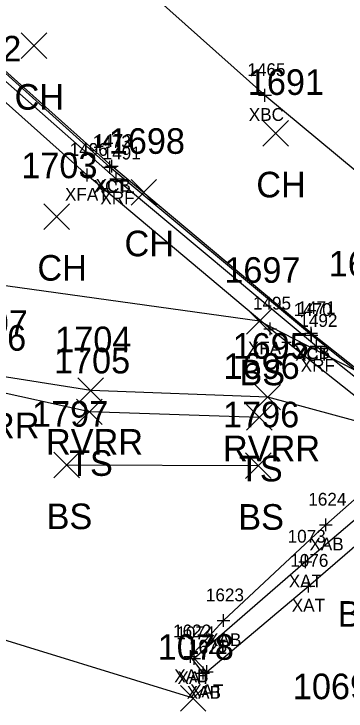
# Model space of a CAD drawing. Extents: x 1616726 to 1619875, y 273782 to 276557.
# Drawn here: x 1616995.8 to 1617021.7, y 276211.5 to 276265.9 of the extents above; entities that cross this region are included whole.
import ezdxf

# ---------------------------------------------------------------- set-up
doc = ezdxf.new("R2010")
doc.units = 0
for name, color, linetype in [('B_A', 7, 'Continuous'), ('B_I', 7, 'Continuous'), ('B_TIC', 7, 'Continuous'), ('BDC', 7, 'Continuous'), ('BELB', 7, 'Continuous'), ('BF', 7, 'Continuous'), ('BR', 7, 'Continuous'), ('BSUBM', 7, 'Continuous'), ('L_A', 7, 'Continuous'), ('L_I', 7, 'Continuous'), ('L_TIC', 7, 'Continuous'), ('LAWE', 7, 'Continuous'), ('LELB', 7, 'Continuous'), ('S_C', 7, 'Continuous')]:
    doc.layers.add(name, color=color, linetype=linetype)

msp = doc.modelspace()

# ---------------------------------------------------------------- linework, layer by layer
at = {"layer": 'B_TIC'}
for p, q in [((1617015.413, 276259.543), (1617015.488, 276259.543)), ((1617003.313, 276253.921), (1617003.388, 276253.921)), ((1617003.452, 276254.007), (1617003.528, 276254.007)), ((1617001.54, 276253.314), (1617001.616, 276253.314)), ((1617003.801, 276253.031), (1617003.877, 276253.031)), ((1617015.82, 276241.312), (1617015.895, 276241.312)), ((1617019.015, 276240.957), (1617019.09, 276240.957)), ((1617019.043, 276240.812), (1617019.119, 276240.812)), ((1617019.442, 276239.958), (1617019.518, 276239.958)), ((1617020.165, 276225.998), (1617020.241, 276225.998)), ((1617018.568, 276223.108), (1617018.643, 276223.108)), ((1617018.802, 276221.224), (1617018.878, 276221.224)), ((1617012.168, 276218.528), (1617012.244, 276218.528)), ((1617009.608, 276215.712), (1617009.683, 276215.712)), ((1617009.878, 276215.569), (1617009.953, 276215.569)), ((1617010.87, 276214.533), (1617010.945, 276214.533)), ((1617010.581, 276214.426), (1617010.656, 276214.426))]:
    msp.add_line(p, q, dxfattribs=at)
for points in [[(1617015.409, 276259.043), (1617015.409, 276260.044)], [(1617014.909, 276259.543), (1617015.909, 276259.543)], [(1617003.309, 276253.421), (1617003.309, 276254.421)], [(1617003.449, 276253.507), (1617003.449, 276254.507)], [(1617001.537, 276252.814), (1617001.537, 276253.814)], [(1617002.809, 276253.921), (1617003.809, 276253.921)], [(1617002.949, 276254.007), (1617003.949, 276254.007)], [(1617001.037, 276253.314), (1617002.037, 276253.314)], [(1617003.798, 276252.531), (1617003.798, 276253.531)], [(1617003.298, 276253.031), (1617004.298, 276253.031)], [(1617015.816, 276240.812), (1617015.816, 276241.812)], [(1617015.316, 276241.312), (1617016.316, 276241.312)], [(1617019.011, 276240.457), (1617019.011, 276241.457)], [(1617019.04, 276240.312), (1617019.04, 276241.312)], [(1617018.511, 276240.957), (1617019.511, 276240.957)], [(1617018.54, 276240.812), (1617019.54, 276240.812)], [(1617019.439, 276239.458), (1617019.439, 276240.458)], [(1617018.939, 276239.958), (1617019.939, 276239.958)], [(1617020.162, 276225.498), (1617020.162, 276226.498)], [(1617019.662, 276225.998), (1617020.662, 276225.998)], [(1617018.564, 276222.608), (1617018.564, 276223.608)], [(1617018.064, 276223.108), (1617019.064, 276223.108)], [(1617018.799, 276220.724), (1617018.799, 276221.724)], [(1617018.299, 276221.224), (1617019.299, 276221.224)], [(1617012.165, 276218.028), (1617012.165, 276219.028)], [(1617011.665, 276218.528), (1617012.665, 276218.528)], [(1617009.604, 276215.212), (1617009.604, 276216.212)], [(1617009.104, 276215.712), (1617010.104, 276215.712)], [(1617009.375, 276215.569), (1617010.375, 276215.569)], [(1617009.875, 276215.069), (1617009.875, 276216.069)], [(1617010.866, 276214.033), (1617010.866, 276215.033)], [(1617010.366, 276214.533), (1617011.366, 276214.533)], [(1617010.577, 276213.926), (1617010.577, 276214.926)], [(1617010.077, 276214.426), (1617011.077, 276214.426)]]:
    msp.add_lwpolyline(points, dxfattribs=at)
at = {"layer": 'BDC'}
for points in [[(1617032.089, 276230.634), (1617019.011, 276240.957), (1617003.449, 276254.007), (1616987.219, 276268.519), (1616972.153, 276283.37), (1616957.519, 276298.646), (1616946.38, 276311.131), (1616940.99, 276317.433)], [(1617031.94, 276230.493), (1617019.04, 276240.812), (1617003.309, 276253.921), (1616987.272, 276268.372), (1616971.94, 276283.404), (1616957.293, 276298.592), (1616946.104, 276311.237), (1616940.906, 276317.316)]]:
    msp.add_lwpolyline(points, dxfattribs=at)
at = {"layer": 'BELB'}
msp.add_lwpolyline([(1616953.623, 276321.315), (1616970.875, 276302.028), (1616987.05, 276285.607), (1616997.927, 276275.138), (1617015.409, 276259.543), (1617031.053, 276246.557), (1617046.388, 276234.455)], dxfattribs=at)
at = {"layer": 'BF'}
msp.add_lwpolyline([(1617030.013, 276230.064), (1617015.816, 276241.312), (1617001.537, 276253.314), (1616989.849, 276263.729), (1616982.397, 276270.726), (1616969.932, 276282.988), (1616958.21, 276295.373), (1616947.149, 276307.449), (1616939.121, 276316.789)], dxfattribs=at)
at = {"layer": 'BR'}
msp.add_lwpolyline([(1616940.542, 276317.169), (1616949.786, 276306.506), (1616958.097, 276297.283), (1616966.707, 276288.28), (1616975.45, 276279.333), (1616984.398, 276270.583), (1616994.032, 276261.605), (1617003.798, 276253.031), (1617019.439, 276239.958), (1617030.784, 276230.919)], dxfattribs=at)
at = {"layer": 'BSUBM'}
for points in [[(1617010.577, 276214.426), (1617009.604, 276215.712), (1617012.165, 276218.528), (1617020.162, 276225.998), (1617024.806, 276230.09), (1617027.157, 276232.146), (1617038.443, 276235.694), (1617050.909, 276239.585), (1617068.456, 276245.114), (1617089.814, 276247.416), (1617090.344, 276244.994)], [(1617029.406, 276230.18), (1617028.346, 276231.06), (1617027.425, 276230.625), (1617018.564, 276223.108), (1617009.875, 276215.569), (1617010.866, 276214.533), (1617018.799, 276221.224), (1617028.471, 276229.537)]]:
    msp.add_lwpolyline(points, dxfattribs=at)
at = {"layer": 'L_TIC'}
for points in [[(1616996.373, 276262.418), (1616998.373, 276264.418)], [(1616998.373, 276262.418), (1616996.373, 276264.418)], [(1617015.246, 276255.569), (1617017.246, 276257.569)], [(1617017.246, 276255.569), (1617015.246, 276257.569)], [(1617004.954, 276250.971), (1617006.954, 276252.971)], [(1617006.954, 276250.971), (1617004.954, 276252.971)], [(1616998.155, 276249.068), (1617000.155, 276251.068)], [(1617000.155, 276249.068), (1616998.155, 276251.068)], [(1617013.974, 276240.9), (1617015.974, 276242.9)], [(1617015.974, 276240.9), (1617013.974, 276242.9)], [(1617000.802, 276235.481), (1617002.802, 276237.481)], [(1617002.802, 276235.481), (1617000.802, 276237.481)], [(1617014.623, 276234.97), (1617016.623, 276236.97)], [(1617016.623, 276234.97), (1617014.623, 276236.97)], [(1617000.705, 276233.825), (1617002.705, 276235.825)], [(1617002.705, 276233.825), (1617000.705, 276235.825)], [(1617013.968, 276233.393), (1617015.968, 276235.393)], [(1617015.968, 276233.393), (1617013.968, 276235.393)], [(1616998.918, 276229.664), (1617000.918, 276231.664)], [(1617000.918, 276229.664), (1616998.918, 276231.664)], [(1617013.884, 276229.615), (1617015.884, 276231.615)], [(1617015.884, 276229.615), (1617013.884, 276231.615)], [(1617008.805, 276211.459), (1617010.805, 276213.459)], [(1617010.805, 276211.459), (1617008.805, 276213.459)]]:
    msp.add_lwpolyline(points, dxfattribs=at)
at = {"layer": 'LAWE'}
msp.add_lwpolyline([(1617025.704, 276233.229), (1617015.623, 276235.97), (1617001.802, 276236.481), (1616993.715, 276237.76), (1616982.576, 276237.202), (1616969.982, 276238.819), (1616958.412, 276240.145), (1616941.628, 276245.844), (1616918.276, 276250.862), (1616897.517, 276255.185), (1616867.227, 276263.214), (1616844.351, 276269.714), (1616814.421, 276281.911), (1616791.447, 276293.204)], dxfattribs=at)
at = {"layer": 'LELB'}
for points in [[(1617180.325, 276288.326), (1617161.431, 276281.848), (1617137.104, 276278.445), (1617120.409, 276268.034), (1617108.303, 276262.949), (1617094.244, 276258.017), (1617079.483, 276248.101), (1617068.225, 276247.781), (1617049.151, 276245.503), (1617035.056, 276240.813), (1617026.009, 276236.235), (1617014.974, 276241.9), (1616972.474, 276247.818), (1616960.605, 276245.765), (1616944.032, 276250.468), (1616920.652, 276257.271), (1616898.689, 276263.021), (1616845.503, 276278.094), (1616816.834, 276290.556), (1616792.378, 276296.226)], [(1617014.968, 276234.393), (1617001.705, 276234.825), (1616993.642, 276236.6)], [(1617014.884, 276230.615), (1616999.918, 276230.664)], [(1617009.805, 276212.459), (1616992.204, 276217.872)]]:
    msp.add_lwpolyline(points, dxfattribs=at)

# ---------------------------------------------------------------- texts
at = {"layer": 'B_A'}
for s, p in [('XBC', (1617014.145, 276257.543)), ('XCT', (1617002.03, 276251.921)), ('XCB', (1617002.185, 276252.007)), ('XFAT', (1616999.793, 276251.314)), ('XRF', (1617002.558, 276251.031)), ('XFAT', (1617014.072, 276239.312)), ('XCB', (1617017.747, 276238.957)), ('XCT', (1617017.76, 276238.812)), ('XRF', (1617018.199, 276237.958)), ('XAB', (1617018.882, 276223.998)), ('XAT', (1617017.269, 276221.108)), ('XAT', (1617017.503, 276219.224)), ('XAB', (1617010.885, 276216.528)), ('XAB', (1617008.325, 276213.712)), ('XAT', (1617008.579, 276213.569)), ('XAB', (1617009.298, 276212.426)), ('XAT', (1617009.571, 276212.533))]:
    msp.add_text(s, height=1, dxfattribs=at).set_placement(p)
at = {"layer": 'B_I'}
for s, p in [('1465', (1617014.039, 276261.043)), ('1473', (1617001.963, 276255.421)), ('1472', (1617002.102, 276255.507)), ('1496', (1617000.163, 276254.814)), ('1491', (1617002.735, 276254.531)), ('1495', (1617014.47, 276242.812)), ('1470', (1617017.65, 276242.312)), ('1471', (1617017.948, 276242.457)), ('1492', (1617018.093, 276241.458)), ('1624', (1617018.792, 276227.498)), ('1073', (1617017.179, 276224.608)), ('1076', (1617017.385, 276222.724)), ('1623', (1617010.795, 276220.028)), ('1622', (1617008.234, 276217.212)), ('1074', (1617008.489, 276217.069)), ('1075', (1617009.48, 276216.033)), ('1621', (1617009.491, 276215.926))]:
    msp.add_text(s, height=1, dxfattribs=at).set_placement(p)
at = {"layer": 'L_A'}
for s, p in [('CH', (1616995.861, 276258.418)), ('CH', (1617014.734, 276251.569)), ('CH', (1617004.443, 276246.971)), ('CH', (1616997.643, 276245.068)), ('BS', (1617013.415, 276236.9)), ('RVRR', (1616990.226, 276232.76)), ('RVRR', (1616998.314, 276231.481)), ('RVRR', (1617012.135, 276230.97)), ('TS', (1617000.115, 276229.825)), ('TS', (1617013.378, 276229.393)), ('BS', (1616998.359, 276225.664)), ('BS', (1617013.325, 276225.615))]:
    msp.add_text(s, height=2, dxfattribs=at).set_placement(p)
at = {"layer": 'L_I'}
for s, p in [('1702', (1616990.439, 276262.182)), ('1691', (1617014.072, 276259.569)), ('1698', (1617003.214, 276254.971)), ('1703', (1616996.384, 276253.068)), ('1692', (1617020.391, 276245.393)), ('1697', (1617012.234, 276244.9)), ('1707', (1616990.943, 276240.76)), ('1706', (1616990.815, 276239.6)), ('1704', (1616999.03, 276239.481)), ('1695', (1617012.883, 276238.97)), ('1705', (1616998.934, 276237.825)), ('1696', (1617012.173, 276237.393)), ('1797', (1616997.225, 276233.664)), ('1796', (1617012.136, 276233.615)), ('1078', (1617007.033, 276215.459)), ('1069', (1617017.587, 276212.385))]:
    msp.add_text(s, height=2, dxfattribs=at).set_placement(p)
at = {"layer": 'S_C'}
msp.add_text('BRIDGE WARNING', height=2, dxfattribs=at).set_placement((1617021.095, 276218.045))

doc.saveas('drawing.dxf')
